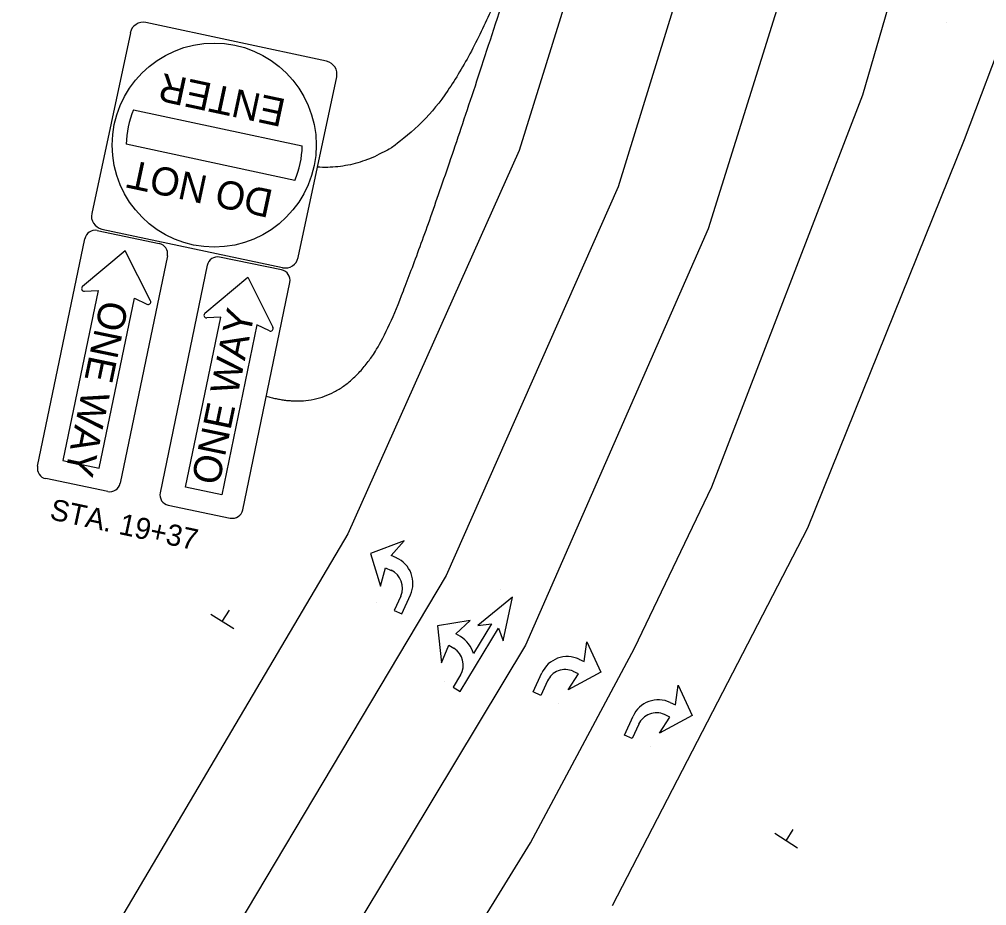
# Model space of a CAD drawing. Extents: x 1847379 to 1850904, y 217032 to 220169.
# Drawn here: x 1849441.6 to 1849556.2, y 218604.4 to 218709.4 of the extents above; entities that cross this region are included whole.
import ezdxf

# ---------------------------------------------------------------- set-up
doc = ezdxf.new("R2010")
doc.units = 0
for name, color, linetype in [('BR_P_Gen_Approach_Slab_Hidden', 7, 'Continuous'), ('PM_P_Cells', 7, 'Continuous'), ('PM_X_Cells', 7, 'Continuous'), ('PM_X_Channelizing_Line', 7, 'Continuous'), ('SN_X_Public', 7, 'Continuous'), ('SN_X_Text', 7, 'Continuous')]:
    doc.layers.add(name, color=color, linetype=linetype)

msp = doc.modelspace()

# ---------------------------------------------------------------- linework, layer by layer
at = {"layer": 'BR_P_Gen_Approach_Slab_Hidden'}
for p, q in [((1849517.42, 218747.13), (1849500.81, 218693.84)), ((1849553.54, 218695.13), (1849560.29, 218713.02)), ((1849535, 218649.16), (1849553.54, 218695.13)), ((1849500.81, 218693.84), (1849480.52, 218648.45)), ((1849480.52, 218648.45), (1849444.93, 218588.18)), ((1849511.85, 218604.43), (1849535, 218649.16))]:
    msp.add_line(p, q, dxfattribs=at)
at = {"layer": 'PM_P_Cells'}
for p, q in [((1849498.59, 218641.82), (1849498.59, 218641.82)), ((1849500.02, 218640.96), (1849495.94, 218637.58)), ((1849498.91, 218635.78), (1849500.02, 218640.96)), ((1849495.03, 218638.2), (1849491.14, 218637.57)), ((1849493.3, 218636.63), (1849495.03, 218638.2)), ((1849495.94, 218637.58), (1849497.52, 218637.8)), ((1849491.14, 218637.57), (1849491.6, 218633.17)), ((1849493.84, 218629.79), (1849498.37, 218637.28)), ((1849498.37, 218637.28), (1849498.91, 218635.78)), ((1849493.87, 218636.29), (1849493.3, 218636.63)), ((1849491.6, 218633.17), (1849492.47, 218635.26)), ((1849492.47, 218635.26), (1849493.08, 218634.9)), ((1849491.99, 218630.92), (1849491.99, 218630.92)), ((1849493.85, 218631.75), (1849492.98, 218630.31)), ((1849492.98, 218630.31), (1849493.84, 218629.79))]:
    msp.add_line(p, q, dxfattribs=at)
msp.add_lwpolyline([(1849497.52, 218637.8), (1849495.39, 218634.29)], dxfattribs=at)
for centre, radius, start, end in [((1849492.22, 218633.45), 3.28, 14.7442, 59.6992), ((1849491.89, 218632.93), 2.3, 328.7907, 58.7907)]:
    msp.add_arc(centre, radius, start, end, dxfattribs=at)
at = {"layer": 'PM_X_Cells'}
for p, q in [((1849551.4, 218709.02), (1849551.4, 218709.02)), ((1849551.4, 218709.02), (1849551.4, 218709.02)), ((1849487.2, 218647.64), (1849483.21, 218646.11)), ((1849487.2, 218647.64), (1849483.21, 218646.11)), ((1849485.67, 218645.88), (1849487.2, 218647.64)), ((1849485.67, 218645.88), (1849487.2, 218647.64)), ((1849487.2, 218647.64), (1849487.2, 218647.64)), ((1849487.2, 218647.64), (1849487.2, 218647.64)), ((1849483.21, 218646.11), (1849484.38, 218642.24)), ((1849483.21, 218646.11), (1849484.38, 218642.24)), ((1849486.27, 218645.6), (1849485.67, 218645.88)), ((1849486.27, 218645.6), (1849485.67, 218645.88)), ((1849484.38, 218642.24), (1849485, 218644.42)), ((1849484.38, 218642.24), (1849485, 218644.42)), ((1849485, 218644.42), (1849485.64, 218644.13)), ((1849485, 218644.42), (1849485.64, 218644.13)), ((1849486.93, 218638.98), (1849487.95, 218641.24)), ((1849486.93, 218638.98), (1849487.95, 218641.24)), ((1849483.89, 218640.36), (1849483.89, 218640.36)), ((1849483.89, 218640.36), (1849483.89, 218640.36)), ((1849486.79, 218641.09), (1849486.02, 218639.39)), ((1849486.79, 218641.09), (1849486.02, 218639.39)), ((1849486.02, 218639.39), (1849486.93, 218638.98)), ((1849486.02, 218639.39), (1849486.93, 218638.98)), ((1849508.51, 218633.33), (1849508.83, 218635.65)), ((1849508.51, 218633.33), (1849508.83, 218635.65)), ((1849508.83, 218635.65), (1849508.83, 218635.65)), ((1849508.83, 218635.65), (1849510.5, 218632.08)), ((1849508.83, 218635.65), (1849508.83, 218635.65)), ((1849508.83, 218635.65), (1849510.5, 218632.08)), ((1849507.9, 218633.61), (1849508.51, 218633.33)), ((1849507.9, 218633.61), (1849508.51, 218633.33)), ((1849510.5, 218632.08), (1849506.62, 218629.98)), ((1849510.5, 218632.08), (1849506.62, 218629.98)), ((1849507.85, 218631.88), (1849507.21, 218632.17)), ((1849507.85, 218631.88), (1849507.21, 218632.17)), ((1849502.48, 218629.74), (1849503.51, 218632)), ((1849502.48, 218629.74), (1849503.51, 218632)), ((1849504.17, 218631.03), (1849503.4, 218629.33)), ((1849504.17, 218631.03), (1849503.4, 218629.33)), ((1849506.62, 218629.98), (1849507.85, 218631.88)), ((1849506.62, 218629.98), (1849507.85, 218631.88)), ((1849519.31, 218628.22), (1849519.63, 218630.53)), ((1849519.31, 218628.22), (1849519.63, 218630.53)), ((1849519.63, 218630.53), (1849519.63, 218630.53)), ((1849519.63, 218630.53), (1849521.3, 218626.96)), ((1849519.63, 218630.53), (1849519.63, 218630.53)), ((1849519.63, 218630.53), (1849521.3, 218626.96)), ((1849503.4, 218629.33), (1849502.48, 218629.74)), ((1849503.4, 218629.33), (1849502.48, 218629.74)), ((1849505.52, 218628.36), (1849505.52, 218628.36)), ((1849505.52, 218628.36), (1849505.52, 218628.36)), ((1849518.7, 218628.49), (1849519.31, 218628.22)), ((1849518.7, 218628.49), (1849519.31, 218628.22)), ((1849513.29, 218624.62), (1849514.31, 218626.88)), ((1849513.29, 218624.62), (1849514.31, 218626.88)), ((1849521.3, 218626.96), (1849517.42, 218624.86)), ((1849521.3, 218626.96), (1849517.42, 218624.86)), ((1849517.42, 218624.86), (1849518.65, 218626.76)), ((1849517.42, 218624.86), (1849518.65, 218626.76)), ((1849518.65, 218626.76), (1849518.01, 218627.05)), ((1849518.65, 218626.76), (1849518.01, 218627.05)), ((1849514.97, 218625.91), (1849514.2, 218624.21)), ((1849514.97, 218625.91), (1849514.2, 218624.21)), ((1849514.2, 218624.21), (1849513.29, 218624.62)), ((1849514.2, 218624.21), (1849513.29, 218624.62)), ((1849516.32, 218623.25), (1849516.32, 218623.25)), ((1849516.32, 218623.25), (1849516.32, 218623.25))]:
    msp.add_line(p, q, dxfattribs=at)
for centre, radius, start, end in [((1849484.96, 218642.59), 3.28, 335.5953, 66.5038), ((1849484.96, 218642.59), 3.28, 335.5953, 66.5038), ((1849484.7, 218642.04), 2.3, 335.5953, 65.5953), ((1849484.7, 218642.04), 2.3, 335.5953, 65.5953), ((1849506.5, 218630.64), 3.28, 64.6868, 155.5953), ((1849506.5, 218630.64), 3.28, 64.6868, 155.5953), ((1849506.26, 218630.08), 2.3, 65.5953, 155.5953), ((1849506.26, 218630.08), 2.3, 65.5953, 155.5953), ((1849517.3, 218625.52), 3.28, 64.6868, 155.5953), ((1849517.3, 218625.52), 3.28, 64.6868, 155.5953), ((1849517.06, 218624.96), 2.3, 65.5953, 155.5953), ((1849517.06, 218624.96), 2.3, 65.5953, 155.5953)]:
    msp.add_arc(centre, radius, start, end, dxfattribs=at)
at = {"layer": 'PM_X_Channelizing_Line'}
for points in [[(1849532.3, 218753.65), (1849512.53, 218689.53), (1849492.16, 218643.5), (1849455.1, 218581.32), (1849423.31, 218533.88), (1849422.33, 218532.18), (1849391.57, 218486.81), (1849363.72, 218433.84)], [(1849543.85, 218750.54), (1849523.2, 218684.58), (1849501.55, 218635.29), (1849465.6, 218575.53), (1849432.35, 218525.21), (1849402.87, 218481.04), (1849375.64, 218428.2)], [(1849386.41, 218422.68), (1849398.05, 218448.32), (1849427.84, 218496.92), (1849472.39, 218563.54), (1849502.15, 218611.88), (1849514.47, 218634.91), (1849523.63, 218654.01), (1849541.52, 218700.42), (1849555.12, 218747.32)]]:
    msp.add_lwpolyline(points, dxfattribs=at)
at = {"layer": 'SN_X_Public'}
for p, q in [((1849455.16, 218698.65), (1849475.12, 218694.38)), ((1849474.24, 218690.3), (1849454.28, 218694.58)), ((1849454.17, 218681.98), (1849449.11, 218677.72)), ((1849457.15, 218676.05), (1849454.17, 218681.98)), ((1849463.6, 218674.58), (1849468.69, 218678.83)), ((1849468.69, 218678.83), (1849471.65, 218672.91)), ((1849450.96, 218677.25), (1849446.79, 218657.12)), ((1849449.32, 218677.17), (1849450.96, 218677.25)), ((1849451.08, 218656.23), (1849455.25, 218676.36)), ((1849455.25, 218676.36), (1849456.73, 218675.63)), ((1849461.3, 218653.97), (1849465.47, 218674.1)), ((1849465.47, 218674.1), (1849463.82, 218674.02)), ((1849469.75, 218673.21), (1849465.59, 218653.08)), ((1849471.23, 218672.49), (1849469.75, 218673.21)), ((1849446.79, 218657.12), (1849451.08, 218656.23)), ((1849465.59, 218653.08), (1849461.3, 218653.97)), ((1849465.66, 218638.06), (1849466.51, 218639.41)), ((1849467.01, 218637.21), (1849464.3, 218638.92)), ((1849533.78, 218611.25), (1849531.08, 218612.96)), ((1849532.43, 218612.1), (1849533.28, 218613.46))]:
    msp.add_line(p, q, dxfattribs=at)
for points in [[(1849478.01, 218704.41), (1849456.62, 218708.99)], [(1849454.77, 218707.79), (1849450.19, 218686.4)], [(1849474.63, 218681.17), (1849479.21, 218702.56)], [(1849450.84, 218684.36), (1849458.19, 218682.84)], [(1849451.39, 218684.54), (1849472.78, 218679.97)], [(1849443.78, 218656.47), (1849449.37, 218683.39)], [(1849459.16, 218681.36), (1849453.58, 218654.44)], [(1849463.87, 218680.25), (1849458.29, 218653.32)], [(1849472.69, 218679.7), (1849465.34, 218681.22)], [(1849468.09, 218651.29), (1849473.66, 218678.22)], [(1849452.1, 218653.47), (1849444.75, 218654.99)], [(1849459.26, 218651.84), (1849466.61, 218650.32)]]:
    msp.add_lwpolyline(points, dxfattribs=at)
msp.add_circle((1849464.7, 218694.48), 12.08, dxfattribs=at)
for centre, radius, start, end in [((1849456.29, 218707.46), 1.56, 77.9213, 167.9213), ((1849477.68, 218702.88), 1.56, 347.9213, 77.9213), ((1849464.7, 218694.48), 10.42, 156.3844, 179.4583), ((1849464.7, 218694.48), 10.42, 336.3844, 359.4583), ((1849451.72, 218686.07), 1.56, 167.9213, 257.9213), ((1849450.59, 218683.14), 1.25, 78.2867, 168.2867), ((1849457.93, 218681.62), 1.25, 348.2867, 78.2867), ((1849465.09, 218679.99), 1.25, 78.3095, 168.3095), ((1849473.11, 218681.49), 1.56, 257.9213, 347.9213), ((1849472.43, 218678.47), 1.25, 348.3095, 78.3095), ((1849449.31, 218677.48), 0.314, 129.9142, 272.5299), ((1849456.87, 218675.91), 0.314, 244.0693, 26.6287), ((1849463.8, 218674.34), 0.314, 129.9675, 272.5269), ((1849471.37, 218672.77), 0.314, 244.0663, 26.682), ((1849445.01, 218656.21), 1.25, 168.2867, 258.2867), ((1849452.35, 218654.69), 1.25, 258.2867, 348.2867), ((1849459.52, 218653.06), 1.25, 168.3095, 258.3095), ((1849466.86, 218651.54), 1.25, 258.3095, 348.3095)]:
    msp.add_arc(centre, radius, start, end, dxfattribs=at)
at = {"layer": 'SN_X_Text'}
for points in [[(1849510.02, 218753.21), (1849508.01, 218740.25), (1849503.62, 218723.05), (1849488.22, 218691.24), (1849476.92, 218691.86)], [(1849470.87, 218664.76), (1849480.41, 218661.91), (1849490.53, 218684.65), (1849504.41, 218728.93)]]:
    msp.add_open_spline(points, degree=2, dxfattribs=at)

# ---------------------------------------------------------------- texts
at = {"layer": 'SN_X_Public'}
for s, rotation, p in [('ENTER', 167.9213, (1849473.33, 218699.87)), ('DO NOT', 167.9213, (1849471.84, 218689.11)), ('ONE WAY', 258.2867, (1849451.29, 218676.24)), ('ONE WAY', 78.3095, (1849465.26, 218654.09))]:
    msp.add_text(s, height=3.333, rotation=rotation, dxfattribs=at).set_placement(p)
at = {"layer": 'SN_X_Text'}
msp.add_text('STA. 19+37', height=2.5, rotation=347.9213, dxfattribs=at).set_placement((1849445.11, 218650.2))

doc.saveas('drawing.dxf')
